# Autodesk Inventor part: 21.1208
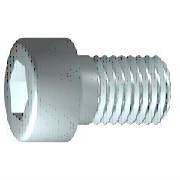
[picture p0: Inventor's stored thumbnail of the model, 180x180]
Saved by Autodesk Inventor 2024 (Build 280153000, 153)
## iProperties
Created: 2006-02
Part Number: 21.1208
Material: Steel, Mild
Description: M8 x 35 SHCS
Document SubType Name: Modeling
Standard: DIN 7984
Designer: Andy Moles
Standards Organization: DIN
Language: en-US
Size Designation: M8 x 35
Categories: <MemberInstance><Categories><Category DisplayName="Fasteners" InternalName="e4da775c-781d-43d5-af7c-5136215cf5a6" Mnemonic="FSTN"><Category DisplayName="Bolts"
Density: 7.85 g/cm^3
Mass: 18.1662 g
Surface Area: 13.9466 cm^2
Volume: 2.31416 cm^3
Vendor: S
Appearance: Zinc
Author: Andy Moles
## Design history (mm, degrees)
body "Solid1"
workplane "Work Plane1"
revolve "Body" stored, may be unused: angle "d10" = 90 deg
sketch "Sketch2"
  geometry: L1 (0, -9.1)-(0, 9.1) reference; L2 (-9.1, 0)-(9.1, 0) reference; L3 (2.887, 0)-(1.443, -2.5); L4 (1.443, -2.5)-(-1.443, -2.5); L5 (-1.443, -2.5)-(-2.887, 0); L6 (-2.887, 0)-(-1.443, 2.5); L7 (-1.443, 2.5)-(1.443, 2.5); L8 (1.443, 2.5)-(2.887, 0); 2 further points
  constraints: 12 end point, 1 coincident, 1 horizontal alignment, 1 point on line, 12 other
extrude "Slot" join sketch "Sketch2" stored distance "d11" = 10; taper "d12" = 0 deg
fillet "Fillet1" dims "d17" = 0.8 (= RR)
feature "Thread" dims "d13" = 22 (= GEL), "d14" = 0
chamfer "Chamfer1" distance "d15" = 0.76681 (= -0.5 x SPD + 0.5 x GD); stored, may be unused: second distance "d16" = 0.76681 (= GUL), angle "d27" = 45 deg
sketch "Sketch1"
  geometry: L1 (0.467, 0)-(35, 0); L2 (35, 0)-(35, 4); L3 (35, 4)-(13, 4); L4 (13, 4)-(12.233, 4); L5 (12.233, 4)-(0, 4); L6 (0, 4)-(0, 6.5); L7 (0, 6.5)-(-5, 6.5); L8 (-5, 6.5)-(-5, 2.887); L9 (-5, 2.887)-(-1.2, 2.887); L10 (-1.2, 2.887)-(0.467, 0); L11 (-13, 0)-(43, 0) reference; L12 (0, -1.3)-(0, 7.8) reference; L13 (13, 4)-(0, 4)
  constraints: 22 end point, 6 parallel, 2 collinear, 2 perpendicular, 1 horizontal, 1 point on line
  dimensions: "d1" = 22 distance from line of L3.end L2 (= GEL); "d2" = 0.76691 distance of L4.end L3.end (computed from GAL); "d3" = 5 distance between parallel lines of L8 L6 (= KOH); "d4" = 3.8 distance of L8.end L9.end (= INTI); "d5" = 60 deg angle of L10 L1; "d6" = 8 diameter of L3 L1 (= GD); "d7" = 8 diameter of L5 L1 (= BDM); "d8" = 5.7735 diameter of L9 L1 (= 1.1547 x SW); "d9" = 13 diameter of L7 L1 (= KOD); "d26" = 35 distance between parallel lines of L12 L2 (= NLG)
other parameters: "GD" = 8 (= NND) [user parameter; used in 2 equation terms], "NLG" = 35 [user parameter; used in 1 equation term], "GEL" = 22 [user parameter; used in 2 equation terms], "KOD" = 13 [user parameter; used in 1 equation term], "KOH" = 5 [user parameter; used in 1 equation term], "INTI" = 3.8 [user parameter; used in 1 equation term], "GAL" = 0.76681 (= 0.61345 x PTC) [user parameter; used in 1 equation term], "GUL" = 0.76681 (= 0.61345 x PTC) [user parameter; used in 1 equation term], "BDM" = 8 (= NND) [user parameter; used in 1 equation term], "SW" = 5 [user parameter; used in 2 equation terms], "RR" = 0.8 [user parameter; used in 1 equation term], "SPD" = 6.46637 (= NND - 1.2269 x PTC) [user parameter; used in 1 equation term], "d19" = 0, "d28" = 0, "d29" = 0, "TOA" = 30 deg [user parameter], "GD1" = 6.46637 (= THREADDIA - 1.2269 x PTC) [user parameter], "THREADDIA" = 8 [user parameter; used in 1 equation term], "FAWI" = 45 deg [user parameter], "ANG" = 120 deg [user parameter], "TPU" = 8 (computed from PTC) [user parameter], "PTC" = 1.25 [user parameter; used in 5 equation terms], "NND" = 8 [user parameter; used in 3 equation terms], "E0" = 5.775 (= 1.155 x SW) [user parameter]
